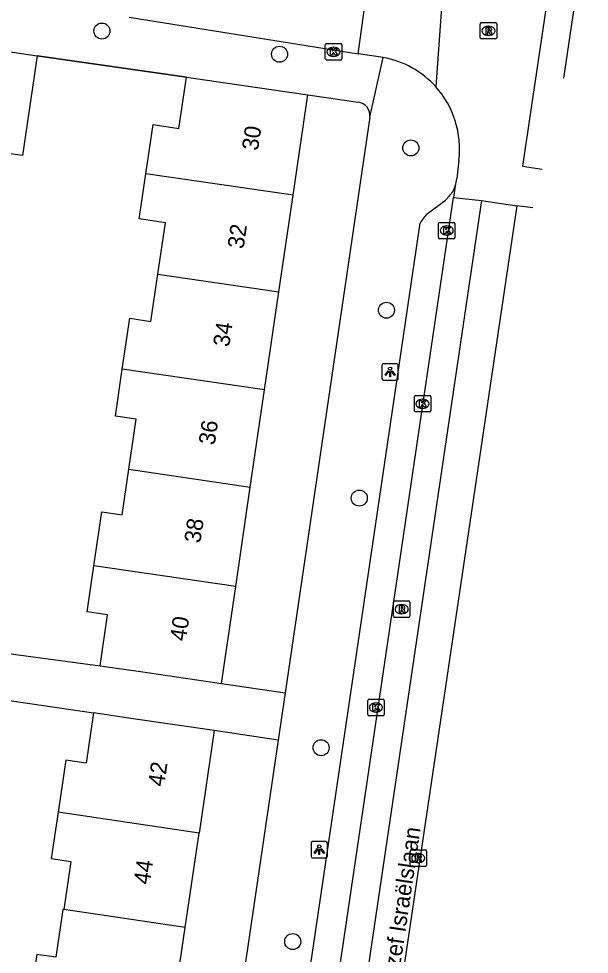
# Model space of a CAD drawing. Extents: x 163686 to 164493, y 382719 to 383870.
# Drawn here: x 164188.2 to 164223.1, y 382940.9 to 382998.1 of the extents above; entities that cross this region are included whole.
import ezdxf

# ---------------------------------------------------------------- set-up
doc = ezdxf.new("R2010")
doc.units = 0
for name, color, linetype in [('IMGEO_Boom', 7, 'Continuous'), ('IMGEO_Fietspad_gesloten', 7, 'Continuous'), ('IMGEO_Kolk', 7, 'Continuous'), ('IMGEO_Lichtpunt', 7, 'Continuous'), ('IMGEO_Muur', 7, 'Continuous'), ('IMGEO_Openbare_ruimte_label', 7, 'Continuous'), ('IMGEO_Pand', 7, 'Continuous'), ('IMGEO_Pand_nummerreeks', 7, 'Continuous'), ('IMGEO_Rijbaan_lokaal_gesloten', 7, 'Continuous'), ('IMGEO_Rijbaan_lokaal_open', 7, 'Continuous'), ('IMGEO_Rioolput', 7, 'Continuous'), ('IMGEO_Voetpad_open', 7, 'Continuous')]:
    doc.layers.add(name, color=color, linetype=linetype)

msp = doc.modelspace()

# ---------------------------------------------------------------- linework, layer by layer
at = {"layer": 'IMGEO_Boom'}
for centre in [(164193.313, 382997.307), (164204.165, 382995.886), (164212.187, 382990.163), (164210.699, 382980.253), (164209.038, 382968.78), (164206.705, 382953.533), (164204.969, 382941.692)]:
    msp.add_circle(centre, 0.489, dxfattribs=at)
at = {"layer": 'IMGEO_Fietspad_gesloten'}
msp.add_lwpolyline([(164204.438, 382917.1), (164214.798, 382987.144)], dxfattribs=at)
at = {"layer": 'IMGEO_Kolk'}
for p, q in [((164206.963, 382995.61), (164206.963, 382996.462)), ((164207.038, 382996.536), (164207.89, 382996.536)), ((164207.451, 382996.316), (164207.476, 382996.316)), ((164207.964, 382996.462), (164207.964, 382995.61)), ((164207.474, 382995.756), (164207.449, 382995.756)), ((164207.89, 382995.536), (164207.038, 382995.536)), ((164213.881, 382984.693), (164213.881, 382985.545)), ((164213.956, 382985.619), (164214.808, 382985.619)), ((164214.369, 382985.399), (164214.394, 382985.399)), ((164214.882, 382985.545), (164214.882, 382984.693)), ((164214.392, 382984.839), (164214.367, 382984.839)), ((164214.808, 382984.619), (164213.956, 382984.619)), ((164212.476, 382975.039), (164213.328, 382975.039)), ((164212.401, 382974.113), (164212.401, 382974.965)), ((164212.889, 382974.819), (164212.914, 382974.819)), ((164213.402, 382974.965), (164213.402, 382974.113)), ((164213.328, 382974.039), (164212.476, 382974.039)), ((164212.912, 382974.259), (164212.887, 382974.259)), ((164209.552, 382955.56), (164209.552, 382956.412)), ((164209.627, 382956.486), (164210.479, 382956.486)), ((164210.04, 382956.266), (164210.065, 382956.266)), ((164210.553, 382956.412), (164210.553, 382955.56)), ((164210.063, 382955.706), (164210.038, 382955.706)), ((164210.479, 382955.486), (164209.627, 382955.486))]:
    msp.add_line(p, q, dxfattribs=at)
for points in [[(164206.963, 382995.61), (164206.963, 382996.462)], [(164207.038, 382996.536), (164207.89, 382996.536)], [(164207.284, 382996.236), (164207.407, 382996.236), (164207.407, 382996.085), (164207.537, 382996.236), (164207.701, 382996.236), (164207.555, 382996.085), (164207.708, 382995.836), (164207.556, 382995.836), (164207.471, 382996), (164207.407, 382995.933), (164207.407, 382995.836), (164207.284, 382995.836), (164207.284, 382996.236)], [(164207.964, 382996.462), (164207.964, 382995.61)], [(164207.89, 382995.536), (164207.038, 382995.536)], [(164213.881, 382984.693), (164213.881, 382985.545)], [(164213.956, 382985.619), (164214.808, 382985.619)], [(164214.202, 382985.319), (164214.325, 382985.319), (164214.325, 382985.168), (164214.455, 382985.319), (164214.619, 382985.319), (164214.473, 382985.168), (164214.626, 382984.919), (164214.474, 382984.919), (164214.389, 382985.083), (164214.325, 382985.016), (164214.325, 382984.919), (164214.202, 382984.919), (164214.202, 382985.319)], [(164214.882, 382985.545), (164214.882, 382984.693)], [(164214.808, 382984.619), (164213.956, 382984.619)], [(164212.476, 382975.039), (164213.328, 382975.039)], [(164212.401, 382974.113), (164212.401, 382974.965)], [(164212.722, 382974.739), (164212.845, 382974.739), (164212.845, 382974.588), (164212.975, 382974.739), (164213.139, 382974.739), (164212.993, 382974.588), (164213.146, 382974.339), (164212.994, 382974.339), (164212.909, 382974.503), (164212.845, 382974.436), (164212.845, 382974.339), (164212.722, 382974.339), (164212.722, 382974.739)], [(164213.402, 382974.965), (164213.402, 382974.113)], [(164213.328, 382974.039), (164212.476, 382974.039)], [(164209.552, 382955.56), (164209.552, 382956.412)], [(164209.627, 382956.486), (164210.479, 382956.486)], [(164209.873, 382956.186), (164209.996, 382956.186), (164209.996, 382956.035), (164210.126, 382956.186), (164210.29, 382956.186), (164210.144, 382956.035), (164210.297, 382955.786), (164210.145, 382955.786), (164210.06, 382955.95), (164209.996, 382955.883), (164209.996, 382955.786), (164209.873, 382955.786), (164209.873, 382956.186)], [(164210.553, 382956.412), (164210.553, 382955.56)], [(164210.479, 382955.486), (164209.627, 382955.486)]]:
    msp.add_lwpolyline(points, dxfattribs=at)
for centre, start, end in [((164207.04, 382996.46), 91.552, 178.448), ((164207.04, 382996.46), 91.552, 178.448), ((164207.888, 382996.46), 1.552, 88.448), ((164207.888, 382996.46), 1.552, 88.448), ((164207.04, 382995.612), 181.552, 268.448), ((164207.04, 382995.612), 181.552, 268.448), ((164207.888, 382995.612), 271.552, 358.448), ((164207.888, 382995.612), 271.552, 358.448), ((164213.958, 382985.543), 91.552, 178.448), ((164213.958, 382985.543), 91.552, 178.448), ((164214.806, 382985.543), 1.552, 88.448), ((164214.806, 382985.543), 1.552, 88.448), ((164213.958, 382984.695), 181.552, 268.448), ((164213.958, 382984.695), 181.552, 268.448), ((164214.806, 382984.695), 271.552, 358.448), ((164214.806, 382984.695), 271.552, 358.448), ((164212.478, 382974.963), 91.552, 178.448), ((164212.478, 382974.963), 91.552, 178.448), ((164213.326, 382974.963), 1.552, 88.448), ((164213.326, 382974.963), 1.552, 88.448), ((164212.478, 382974.115), 181.552, 268.448), ((164212.478, 382974.115), 181.552, 268.448), ((164213.326, 382974.115), 271.552, 358.448), ((164213.326, 382974.115), 271.552, 358.448), ((164209.629, 382956.41), 91.552, 178.448), ((164209.629, 382956.41), 91.552, 178.448), ((164210.477, 382956.41), 1.552, 88.448), ((164210.477, 382956.41), 1.552, 88.448), ((164209.629, 382955.562), 181.552, 268.448), ((164209.629, 382955.562), 181.552, 268.448), ((164210.477, 382955.562), 271.552, 358.448), ((164210.477, 382955.562), 271.552, 358.448)]:
    msp.add_arc(centre, 0.0765, start, end, dxfattribs=at)
for centre, major_axis, ratio, start_param, end_param in [((164207.45, 382996.036), (-0.387, 0.002), 0.722429, 4.712389, 7.853982), ((164207.475, 382996.036), (-0.39, 0.002), 0.717154, 1.570796, 4.712389), ((164214.368, 382985.119), (-0.387, 0.002), 0.722429, 4.712389, 7.853982), ((164214.393, 382985.119), (-0.39, 0.002), 0.717154, 1.570796, 4.712389), ((164212.888, 382974.539), (-0.387, 0.002), 0.722429, 4.712389, 7.853982), ((164212.913, 382974.539), (-0.39, 0.002), 0.717154, 1.570796, 4.712389), ((164210.039, 382955.986), (-0.387, 0.002), 0.722429, 4.712389, 7.853982), ((164210.064, 382955.986), (-0.39, 0.002), 0.717154, 1.570796, 4.712389)]:
    msp.add_ellipse(centre, major_axis=major_axis, ratio=ratio, start_param=start_param, end_param=end_param, dxfattribs=at)
at = {"layer": 'IMGEO_Lichtpunt'}
for p, q in [((164210.424, 382976.886), (164210.424, 382976.079)), ((164210.424, 382976.886), (164210.424, 382976.079)), ((164211.326, 382976.981), (164210.518, 382976.981)), ((164211.326, 382976.981), (164210.518, 382976.981)), ((164211.42, 382976.079), (164211.42, 382976.886)), ((164211.42, 382976.079), (164211.42, 382976.886)), ((164210.518, 382975.985), (164211.326, 382975.985)), ((164210.518, 382975.985), (164211.326, 382975.985)), ((164206.093, 382947.704), (164206.093, 382946.897)), ((164206.093, 382947.704), (164206.093, 382946.897)), ((164206.995, 382947.799), (164206.187, 382947.799)), ((164206.995, 382947.799), (164206.187, 382947.799)), ((164207.089, 382946.897), (164207.089, 382947.704)), ((164207.089, 382946.897), (164207.089, 382947.704)), ((164206.187, 382946.803), (164206.995, 382946.803)), ((164206.187, 382946.803), (164206.995, 382946.803))]:
    msp.add_line(p, q, dxfattribs=at)
for points in [[(164210.798, 382976.55), (164210.837, 382976.522), (164210.649, 382976.26), (164210.611, 382976.287), (164210.798, 382976.55)], [(164210.9, 382976.502), (164210.947, 382976.502), (164210.947, 382976.18), (164210.9, 382976.18), (164210.9, 382976.502)], [(164211.01, 382976.522), (164211.048, 382976.549), (164211.235, 382976.287), (164211.196, 382976.259), (164211.01, 382976.522)], [(164206.467, 382947.368), (164206.506, 382947.34), (164206.318, 382947.078), (164206.28, 382947.105), (164206.467, 382947.368)], [(164206.569, 382947.32), (164206.616, 382947.32), (164206.616, 382946.998), (164206.569, 382946.998), (164206.569, 382947.32)], [(164206.679, 382947.34), (164206.717, 382947.367), (164206.904, 382947.105), (164206.865, 382947.077), (164206.679, 382947.34)]]:
    msp.add_lwpolyline(points, dxfattribs=at)
for centre in [(164210.923, 382976.684), (164206.592, 382947.502)]:
    msp.add_circle(centre, 0.0994, dxfattribs=at)
for centre, start, end in [((164210.518, 382976.886), 90, 180), ((164210.518, 382976.886), 90, 180), ((164211.326, 382976.886), 0, 90), ((164211.326, 382976.886), 0, 90), ((164210.518, 382976.079), 180, 270), ((164210.518, 382976.079), 180, 270), ((164211.326, 382976.079), 270, 0), ((164211.326, 382976.079), 270, 360), ((164206.187, 382947.704), 90, 180), ((164206.187, 382947.704), 90, 180), ((164206.995, 382947.704), 0, 90), ((164206.995, 382947.704), 0, 90), ((164206.187, 382946.897), 180, 270), ((164206.187, 382946.897), 180, 270), ((164206.995, 382946.897), 270, 0), ((164206.995, 382946.897), 270, 360)]:
    msp.add_arc(centre, 0.0946, start, end, dxfattribs=at)
at = {"layer": 'IMGEO_Muur'}
msp.add_lwpolyline([(164189.351, 382995.796), (164198.479, 382994.495)], dxfattribs=at)
at = {"layer": 'IMGEO_Pand'}
for points in [[(164185.77, 382996.322), (164189.351, 382995.796)], [(164189.351, 382995.796), (164188.455, 382989.698), (164184.868, 382990.188)], [(164195.994, 382988.591), (164196.436, 382991.593), (164198.019, 382991.36), (164198.479, 382994.495)], [(164198.479, 382994.495), (164205.899, 382993.405)], [(164204.998, 382987.271), (164205.899, 382993.405)], [(164196.729, 382982.459), (164197.189, 382985.59), (164195.587, 382985.825), (164195.708, 382986.647), (164195.994, 382988.591)], [(164204.998, 382987.271), (164195.994, 382988.591)], [(164204.131, 382981.374), (164204.998, 382987.271)], [(164194.56, 382976.655), (164195.017, 382979.761), (164196.305, 382979.571), (164196.729, 382982.459)], [(164196.729, 382982.459), (164204.131, 382981.374)], [(164203.25, 382975.38), (164204.131, 382981.374)], [(164194.952, 382970.535), (164195.402, 382973.599), (164194.138, 382973.785), (164194.56, 382976.655)], [(164203.25, 382975.38), (164194.56, 382976.655)], [(164202.378, 382969.445), (164203.25, 382975.38)], [(164192.819, 382964.64), (164193.303, 382967.932), (164194.542, 382967.749), (164194.952, 382970.535)], [(164194.952, 382970.535), (164202.378, 382969.445)], [(164201.485, 382963.37), (164202.378, 382969.445)], [(164193.207, 382958.539), (164193.663, 382961.643), (164192.406, 382961.827), (164192.819, 382964.64)], [(164201.485, 382963.37), (164192.819, 382964.64)], [(164200.615, 382957.451), (164201.485, 382963.37)], [(164193.207, 382958.539), (164195.669, 382958.177), (164200.615, 382957.451)], [(164192.802, 382955.654), (164192.352, 382952.589), (164191.1, 382952.773), (164190.632, 382949.588)], [(164200.164, 382954.572), (164195.218, 382955.299), (164192.802, 382955.654)], [(164200.164, 382954.572), (164199.245, 382948.317)], [(164190.632, 382949.588), (164190.217, 382946.765), (164191.418, 382946.588), (164190.986, 382943.647)], [(164199.245, 382948.317), (164190.632, 382949.588)], [(164198.398, 382942.552), (164199.245, 382948.317)], [(164190.986, 382943.647), (164190.923, 382943.656), (164190.491, 382940.729), (164189.333, 382940.9), (164188.888, 382937.873)], [(164198.398, 382942.552), (164190.986, 382943.647)], [(164197.522, 382936.598), (164198.398, 382942.552)]]:
    msp.add_lwpolyline(points, dxfattribs=at)
at = {"layer": 'IMGEO_Rijbaan_lokaal_gesloten'}
for points in [[(164223.09, 383005.122), (164221.436, 383005.393), (164219.005, 382989.047), (164220.204, 382988.86)], [(164221.531, 382994.431), (164222.675, 383002.126)], [(164218.67, 382986.633), (164207.15, 382909.112)], [(164219.642, 382986.502), (164218.67, 382986.633)]]:
    msp.add_lwpolyline(points, dxfattribs=at)
at = {"layer": 'IMGEO_Rijbaan_lokaal_open'}
for points in [[(164208.972, 382995.917), (164209.725, 383001.347)], [(164214.269, 383001.641), (164213.709, 382993.899)], [(164194.984, 382998.151), (164208.972, 382995.917)], [(164210.49, 382995.695), (164208.972, 382995.917)], [(164215.122, 382989.42), (164214.993, 382988.302)], [(164214.902, 382987.844), (164214.798, 382987.144)], [(164214.798, 382987.144), (164216.497, 382986.958)], [(164216.497, 382986.958), (164205.045, 382909.418)], [(164216.497, 382986.958), (164218.67, 382986.633)]]:
    msp.add_lwpolyline(points, dxfattribs=at)
for centre, radius, start, end in [((164209.478, 382990.098), 5.688, 41.9347, 79.7477), ((164209.481, 382990.103), 5.682, 353.0991, 41.919), ((164213.262, 382988.408), 1.734, 341.0255, 356.4991)]:
    msp.add_arc(centre, radius, start, end, dxfattribs=at)
at = {"layer": 'IMGEO_Rioolput'}
for p, q in [((164216.431, 382996.896), (164216.431, 382997.748)), ((164216.506, 382997.822), (164217.358, 382997.822)), ((164216.919, 382997.602), (164216.944, 382997.602)), ((164217.432, 382997.748), (164217.432, 382996.896)), ((164217.358, 382996.822), (164216.506, 382996.822)), ((164216.942, 382997.042), (164216.917, 382997.042)), ((164211.127, 382961.567), (164211.127, 382962.419)), ((164211.202, 382962.493), (164212.054, 382962.493)), ((164212.128, 382962.419), (164212.128, 382961.567)), ((164211.615, 382962.273), (164211.64, 382962.273)), ((164212.054, 382961.493), (164211.202, 382961.493)), ((164211.638, 382961.713), (164211.613, 382961.713)), ((164212.14, 382946.359), (164212.14, 382947.211)), ((164212.215, 382947.285), (164213.067, 382947.285)), ((164212.628, 382947.065), (164212.653, 382947.065)), ((164213.141, 382947.211), (164213.141, 382946.359)), ((164212.651, 382946.505), (164212.626, 382946.505)), ((164213.067, 382946.285), (164212.215, 382946.285))]:
    msp.add_line(p, q, dxfattribs=at)
for points in [[(164216.431, 382996.896), (164216.431, 382997.748)], [(164216.506, 382997.822), (164217.358, 382997.822)], [(164217.02, 382997.52), (164216.768, 382997.522), (164216.768, 382997.122)], [(164216.768, 382997.122), (164216.892, 382997.122), (164216.892, 382997.284), (164216.903, 382997.284)], [(164216.946, 382997.441), (164216.892, 382997.441), (164216.892, 382997.36)], [(164216.892, 382997.36), (164216.944, 382997.36)], [(164216.95, 382997.255), (164217.021, 382997.122), (164217.161, 382997.122), (164217.096, 382997.248)], [(164217.432, 382997.748), (164217.432, 382996.896)], [(164217.358, 382996.822), (164216.506, 382996.822)], [(164211.127, 382961.567), (164211.127, 382962.419)], [(164211.202, 382962.493), (164212.054, 382962.493)], [(164212.128, 382962.419), (164212.128, 382961.567)], [(164211.716, 382962.191), (164211.464, 382962.193), (164211.464, 382961.793)], [(164211.464, 382961.793), (164211.588, 382961.793), (164211.588, 382961.955), (164211.599, 382961.955)], [(164211.642, 382962.112), (164211.588, 382962.112), (164211.588, 382962.031)], [(164211.588, 382962.031), (164211.64, 382962.031)], [(164211.646, 382961.926), (164211.717, 382961.793), (164211.857, 382961.793), (164211.792, 382961.919)], [(164212.054, 382961.493), (164211.202, 382961.493)], [(164212.14, 382946.359), (164212.14, 382947.211)], [(164212.215, 382947.285), (164213.067, 382947.285)], [(164212.729, 382946.983), (164212.477, 382946.985), (164212.477, 382946.585)], [(164213.141, 382947.211), (164213.141, 382946.359)], [(164212.477, 382946.585), (164212.601, 382946.585), (164212.601, 382946.747), (164212.612, 382946.747)], [(164212.655, 382946.904), (164212.601, 382946.904), (164212.601, 382946.823)], [(164212.601, 382946.823), (164212.653, 382946.823)], [(164212.659, 382946.718), (164212.73, 382946.585), (164212.87, 382946.585), (164212.805, 382946.711)], [(164213.067, 382946.285), (164212.215, 382946.285)]]:
    msp.add_lwpolyline(points, dxfattribs=at)
for centre, radius, start, end in [((164216.508, 382997.746), 0.0765, 91.552, 178.448), ((164216.508, 382997.746), 0.0765, 91.552, 178.448), ((164216.902, 382997.231), 0.0533, 26.0293, 88.6989), ((164216.928, 382997.549), 0.19, 274.7715, 282.9687), ((164216.952, 382997.345), 0.0964, 77.0061, 93.1865), ((164216.966, 382997.402), 0.0378, 276.6634, 79.6772), ((164217.019, 382997.41), 0.109, 350.3612, 89.416), ((164217.017, 382997.41), 0.112, 277.5842, 350.9817), ((164217.001, 382997.195), 0.108, 29.5134, 73.7905), ((164217.356, 382997.746), 0.0765, 1.552, 88.448), ((164217.356, 382997.746), 0.0765, 1.552, 88.448), ((164216.508, 382996.898), 0.0765, 181.552, 268.448), ((164216.508, 382996.898), 0.0765, 181.552, 268.448), ((164217.356, 382996.898), 0.0765, 271.552, 358.448), ((164217.356, 382996.898), 0.0765, 271.552, 358.448), ((164211.204, 382962.417), 0.0765, 91.552, 178.448), ((164211.204, 382962.417), 0.0765, 91.552, 178.448), ((164212.052, 382962.417), 0.0765, 1.552, 88.448), ((164212.052, 382962.417), 0.0765, 1.552, 88.448), ((164211.598, 382961.902), 0.0533, 26.0293, 88.6989), ((164211.624, 382962.22), 0.19, 274.7715, 282.9687), ((164211.648, 382962.016), 0.0964, 77.0061, 93.1865), ((164211.662, 382962.073), 0.0378, 276.6634, 79.6772), ((164211.715, 382962.081), 0.109, 350.3612, 89.416), ((164211.713, 382962.081), 0.112, 277.5842, 350.9817), ((164211.697, 382961.866), 0.108, 29.5134, 73.7905), ((164211.204, 382961.569), 0.0765, 181.552, 268.448), ((164211.204, 382961.569), 0.0765, 181.552, 268.448), ((164212.052, 382961.569), 0.0765, 271.552, 358.448), ((164212.052, 382961.569), 0.0765, 271.552, 358.448), ((164212.217, 382947.209), 0.0765, 91.552, 178.448), ((164212.217, 382947.209), 0.0765, 91.552, 178.448), ((164212.728, 382946.873), 0.109, 350.3612, 89.416), ((164213.065, 382947.209), 0.0765, 1.552, 88.448), ((164213.065, 382947.209), 0.0765, 1.552, 88.448), ((164212.611, 382946.694), 0.0533, 26.0293, 88.6989), ((164212.637, 382947.012), 0.19, 274.7715, 282.9687), ((164212.661, 382946.808), 0.0964, 77.0061, 93.1865), ((164212.675, 382946.865), 0.0378, 276.6634, 79.6772), ((164212.726, 382946.873), 0.112, 277.5842, 350.9817), ((164212.71, 382946.658), 0.108, 29.5134, 73.7905), ((164212.217, 382946.361), 0.0765, 181.552, 268.448), ((164212.217, 382946.361), 0.0765, 181.552, 268.448), ((164213.065, 382946.361), 0.0765, 271.552, 358.448), ((164213.065, 382946.361), 0.0765, 271.552, 358.448)]:
    msp.add_arc(centre, radius, start, end, dxfattribs=at)
for centre, major_axis, ratio, start_param, end_param in [((164216.918, 382997.322), (-0.387, 0.002), 0.722429, 4.712389, 7.853982), ((164216.943, 382997.322), (-0.39, 0.002), 0.717154, 1.570796, 4.712389), ((164211.614, 382961.993), (-0.387, 0.002), 0.722429, 4.712389, 7.853982), ((164211.639, 382961.993), (-0.39, 0.002), 0.717154, 1.570796, 4.712389), ((164212.627, 382946.785), (-0.387, 0.002), 0.722429, 4.712389, 7.853982), ((164212.652, 382946.785), (-0.39, 0.002), 0.717154, 1.570796, 4.712389)]:
    msp.add_ellipse(centre, major_axis=major_axis, ratio=ratio, start_param=start_param, end_param=end_param, dxfattribs=at)
at = {"layer": 'IMGEO_Voetpad_open'}
for points in [[(164198.479, 382994.495), (164189.351, 382995.796)], [(164209.672, 382992.036), (164210.49, 382995.695)], [(164205.899, 382993.405), (164208.965, 382992.962)], [(164209.672, 382992.036), (164204.502, 382956.879)], [(164213.177, 382986.137), (164214.307, 382986.976), (164214.525, 382987.222)], [(164203.103, 382920.184), (164212.763, 382985.574)], [(164184.093, 382959.745), (164193.207, 382958.539)], [(164200.615, 382957.451), (164204.502, 382956.879)], [(164183.618, 382957.003), (164192.802, 382955.654)], [(164204.502, 382956.879), (164204.078, 382953.996)], [(164204.078, 382953.996), (164200.164, 382954.572)], [(164204.078, 382953.996), (164198.79, 382918.042)]]:
    msp.add_lwpolyline(points, dxfattribs=at)
for centre, radius, start, end in [((164208.868, 382992.155), 0.813, 351.605, 83.1184), ((164213.257, 382988.416), 1.741, 316.7238, 340.8353), ((164215.09, 382984.296), 2.655, 136.1093, 151.2332)]:
    msp.add_arc(centre, radius, start, end, dxfattribs=at)

# ---------------------------------------------------------------- texts
at = {"layer": 'IMGEO_Openbare_ruimte_label'}
msp.add_text('Jozef Israëlslaan', height=1, rotation=81.6024, dxfattribs=at).set_placement((164211.326, 382938.688))
at = {"layer": 'IMGEO_Pand_nummerreeks'}
for s, rotation, p in [('30', 81.6393, (164202.846, 382989.961)), ('32', 81.6393, (164201.965, 382983.962)), ('34', 81.6393, (164201.084, 382977.973)), ('36', 81.6393, (164200.203, 382971.981)), ('38', 81.6393, (164199.324, 382965.991)), ('40', 81.6393, (164198.443, 382959.999)), ('42', 81.6395, (164197.111, 382951.122)), ('44', 81.6395, (164196.23, 382945.134))]:
    msp.add_text(s, height=1, rotation=rotation, dxfattribs=at).set_placement(p)

doc.saveas('drawing.dxf')
